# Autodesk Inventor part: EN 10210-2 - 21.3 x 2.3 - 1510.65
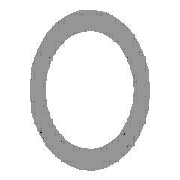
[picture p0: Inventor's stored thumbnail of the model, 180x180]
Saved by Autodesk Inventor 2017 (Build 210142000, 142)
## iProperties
Created: 2017-11
Part Number: EN 10210-2 - 21.3 x 2.3 - 1510.65
Material: Steel, Mild
Description: Pipe
Document SubType Name: Modeling
Standard: DIN
Designer: iusti
Standard Revision: 2006-07
Standards Organization: DIN
Language: en-US
Size Designation: 21.3 x 2.3
Categories: <MemberInstance><Categories><Category DisplayName="Structural Shapes" InternalName="089c4875-fa83-4c05-b084-43b9cc11f5ed" Mnemonic="GRDR"><CategoryParameter Dis
Stock Number: 21.3 x 2.3
Density: 7.85 g/cm^3
Appearance: Semi-Polished
_CCFamilyMember: 1
_CCFamilyDisplayName: DIN EN 10210-2 - Pipe
_FrameMemberDoc: Frame Member File
_Version: 15.0.0
_GetPNFromCC: 1
IsCustomPart: 1
Author: iusti
G_L: 1507.531 mm
G_W: 21.300 mm
G_H: 21.300 mm
+4C4787AB-0BAD-477D-B088-ADA6A635DAD2+CUTDETAIL1: Miter 45.00 deg
+6A921974-C6F6-4C2B-935D-6313A8222D38+CUTDETAIL2: Miter 45.00 deg
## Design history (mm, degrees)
node "Start plane"
node "End plane"
sketch "Sketch"
  geometry: C1 r 8.35 at (0, 0); C2 r 10.65 at (0, 0); 2 further points
  constraints: 3 coincident, 2 centre point
  dimensions: "d0" = 21.3 diameter of C2 (= G_H); "d1" = 2.3 radial gap between concentric circles of C2 C1 (= G_T)
extrude "Body" new body sketch "Sketch" stored distance "d2" = 1507.53069 (= G_L); taper "d3" = 0 deg
node "Driven Length"
  sketch "Sketch3"
    geometry: L1 (0, 0)-(10, 0) reference
    constraints: 2 end point, 1 horizontal
  workplane "Work Plane3"
  sketch "Sketch4"
    geometry: L1 (-2, -10.65)-(12, -10.65) reference; L2 (-2, 1500)-(12, 1500) reference
    dimensions: "d7" = 1510.65 distance between parallel lines of L1 L2 (derived)
workplane "Work Plane4"
split "Split1"
workplane "Work Plane5"
split "Split2"
body "Solid1"
other parameters: "G_H" = 21.3 [user parameter; used in 1 equation term], "G_T" = 2.3 [user parameter; used in 1 equation term], "G_L" = 1507.53069 [user parameter; used in 1 equation term], "G_OFFSET_START" = 10.65 [user parameter; used in 1 equation term], "G_OFFSET_END" = 0 [user parameter; used in 1 equation term], "d4" = -10.65 (= -G_OFFSET_START), "d6" = 90 deg
